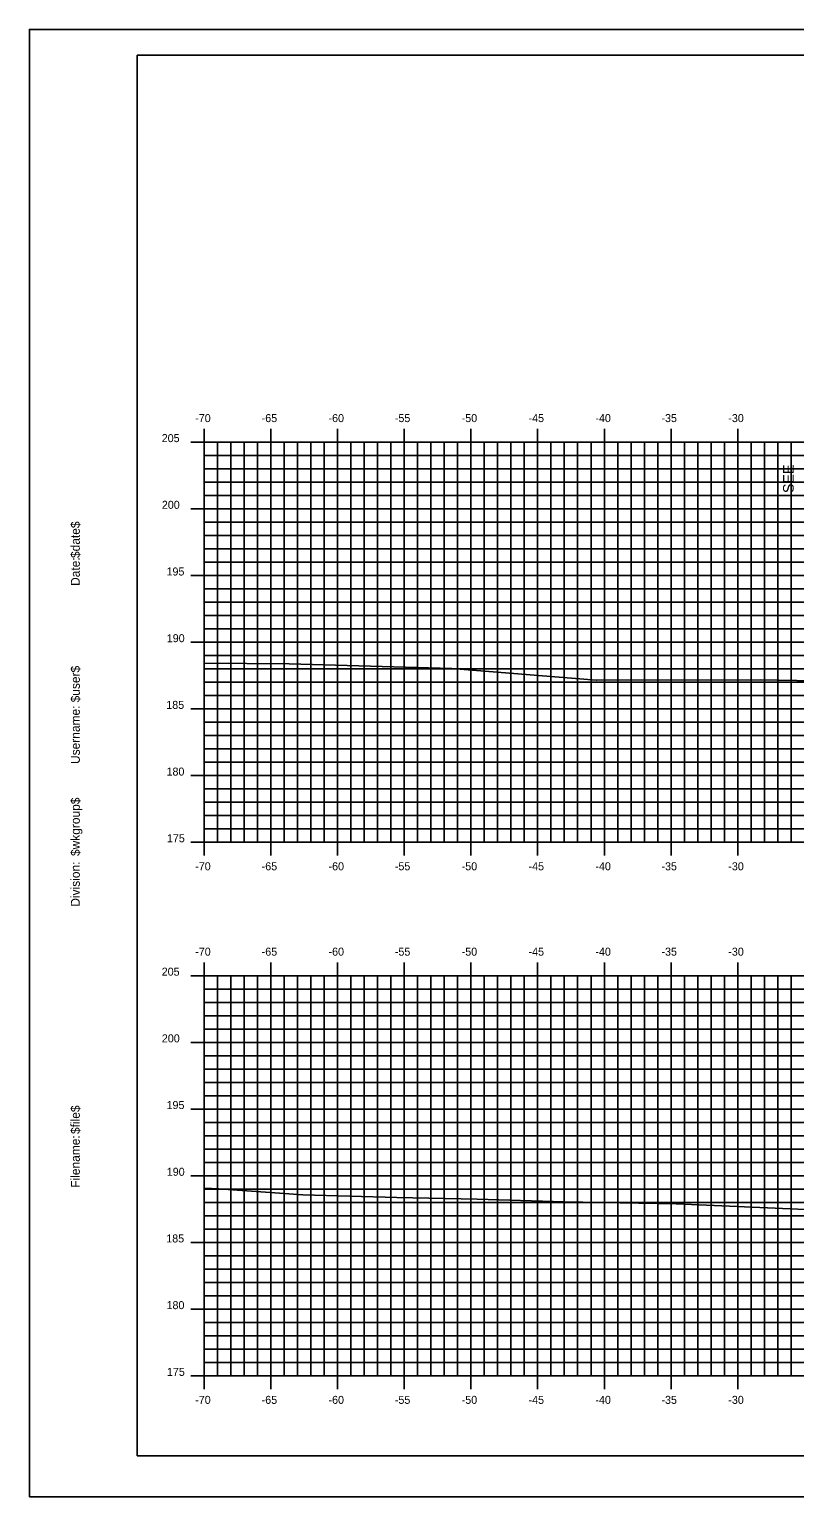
# Model space of a CAD drawing. Extents: x 1723961 to 1724133, y 459560 to 459670.
# Drawn here: x 1723961.4 to 1724018.7, y 459559.6 to 459669.6 of the extents above; entities that cross this region are included whole.
import ezdxf

# ---------------------------------------------------------------- set-up
doc = ezdxf.new("R2010")
doc.units = 0
for name, color, linetype in [('ANNOTATION', 7, 'Continuous'), ('BORDER', 7, 'Continuous'), ('H_V ANNOTATION', 7, 'Continuous'), ('MAJOR', 7, 'Continuous'), ('MINOR', 7, 'Continuous'), ('PLOT BOUNDARY', 7, 'Continuous'), ('S_Roadway_Centerline', 7, 'Continuous')]:
    doc.layers.add(name, color=color, linetype=linetype)

msp = doc.modelspace()

# ---------------------------------------------------------------- linework, layer by layer
at = {"layer": 'BORDER'}
msp.add_lwpolyline([(1723969.47, 459562.61), (1724129.47, 459562.61), (1724129.47, 459667.61), (1723969.47, 459667.61)], close=True, dxfattribs=at)
at = {"layer": 'MAJOR'}
for p, q in [((1723974.47, 459639.61), (1723974.47, 459638.61)), ((1723979.47, 459639.61), (1723979.47, 459638.61)), ((1723984.47, 459639.61), (1723984.47, 459638.61)), ((1723989.47, 459639.61), (1723989.47, 459638.61)), ((1723994.47, 459639.61), (1723994.47, 459638.61)), ((1723999.47, 459639.61), (1723999.47, 459638.61)), ((1724004.47, 459639.61), (1724004.47, 459638.61)), ((1724009.47, 459639.61), (1724009.47, 459638.61)), ((1724014.47, 459639.61), (1724014.47, 459638.61)), ((1723973.47, 459638.61), (1723974.47, 459638.61)), ((1723974.47, 459638.61), (1724114.47, 459638.61)), ((1723974.47, 459608.61), (1723974.47, 459638.61)), ((1723974.47, 459608.61), (1723974.47, 459638.61)), ((1723974.47, 459638.61), (1724114.47, 459638.61)), ((1723979.47, 459608.61), (1723979.47, 459638.61)), ((1723984.47, 459608.61), (1723984.47, 459638.61)), ((1723989.47, 459608.61), (1723989.47, 459638.61)), ((1723994.47, 459608.61), (1723994.47, 459638.61)), ((1723999.47, 459608.61), (1723999.47, 459638.61)), ((1724004.47, 459608.61), (1724004.47, 459638.61)), ((1724009.47, 459608.61), (1724009.47, 459638.61)), ((1724014.47, 459608.61), (1724014.47, 459638.61)), ((1723973.47, 459633.61), (1723974.47, 459633.61)), ((1723974.47, 459633.61), (1724114.47, 459633.61)), ((1723973.47, 459628.61), (1723974.47, 459628.61)), ((1723974.47, 459628.61), (1724114.47, 459628.61)), ((1723973.47, 459623.61), (1723974.47, 459623.61)), ((1723974.47, 459623.61), (1724114.47, 459623.61)), ((1723973.47, 459618.61), (1723974.47, 459618.61)), ((1723974.47, 459618.61), (1724114.47, 459618.61)), ((1723973.47, 459613.61), (1723974.47, 459613.61)), ((1723974.47, 459613.61), (1724114.47, 459613.61)), ((1723973.47, 459608.61), (1723974.47, 459608.61)), ((1723974.47, 459608.61), (1724114.47, 459608.61)), ((1723974.47, 459608.61), (1724114.47, 459608.61)), ((1723974.47, 459607.61), (1723974.47, 459608.61)), ((1723979.47, 459607.61), (1723979.47, 459608.61)), ((1723984.47, 459607.61), (1723984.47, 459608.61)), ((1723989.47, 459607.61), (1723989.47, 459608.61)), ((1723994.47, 459607.61), (1723994.47, 459608.61)), ((1723999.47, 459607.61), (1723999.47, 459608.61)), ((1724004.47, 459607.61), (1724004.47, 459608.61)), ((1724009.47, 459607.61), (1724009.47, 459608.61)), ((1724014.47, 459607.61), (1724014.47, 459608.61)), ((1723974.47, 459599.61), (1723974.47, 459598.61)), ((1723979.47, 459599.61), (1723979.47, 459598.61)), ((1723984.47, 459599.61), (1723984.47, 459598.61)), ((1723989.47, 459599.61), (1723989.47, 459598.61)), ((1723994.47, 459599.61), (1723994.47, 459598.61)), ((1723999.47, 459599.61), (1723999.47, 459598.61)), ((1724004.47, 459599.61), (1724004.47, 459598.61)), ((1724009.47, 459599.61), (1724009.47, 459598.61)), ((1724014.47, 459599.61), (1724014.47, 459598.61)), ((1723973.47, 459598.61), (1723974.47, 459598.61)), ((1723974.47, 459598.61), (1724114.47, 459598.61)), ((1723974.47, 459568.61), (1723974.47, 459598.61)), ((1723974.47, 459568.61), (1723974.47, 459598.61)), ((1723974.47, 459598.61), (1724114.47, 459598.61)), ((1723979.47, 459568.61), (1723979.47, 459598.61)), ((1723984.47, 459568.61), (1723984.47, 459598.61)), ((1723989.47, 459568.61), (1723989.47, 459598.61)), ((1723994.47, 459568.61), (1723994.47, 459598.61)), ((1723999.47, 459568.61), (1723999.47, 459598.61)), ((1724004.47, 459568.61), (1724004.47, 459598.61)), ((1724009.47, 459568.61), (1724009.47, 459598.61)), ((1724014.47, 459568.61), (1724014.47, 459598.61)), ((1723973.47, 459593.61), (1723974.47, 459593.61)), ((1723974.47, 459593.61), (1724114.47, 459593.61)), ((1723973.47, 459588.61), (1723974.47, 459588.61)), ((1723974.47, 459588.61), (1724114.47, 459588.61)), ((1723973.47, 459583.61), (1723974.47, 459583.61)), ((1723974.47, 459583.61), (1724114.47, 459583.61)), ((1723973.47, 459578.61), (1723974.47, 459578.61)), ((1723974.47, 459578.61), (1724114.47, 459578.61)), ((1723973.47, 459573.61), (1723974.47, 459573.61)), ((1723974.47, 459573.61), (1724114.47, 459573.61)), ((1723973.47, 459568.61), (1723974.47, 459568.61)), ((1723974.47, 459568.61), (1724114.47, 459568.61)), ((1723974.47, 459568.61), (1724114.47, 459568.61)), ((1723974.47, 459567.61), (1723974.47, 459568.61)), ((1723979.47, 459567.61), (1723979.47, 459568.61)), ((1723984.47, 459567.61), (1723984.47, 459568.61)), ((1723989.47, 459567.61), (1723989.47, 459568.61)), ((1723994.47, 459567.61), (1723994.47, 459568.61)), ((1723999.47, 459567.61), (1723999.47, 459568.61)), ((1724004.47, 459567.61), (1724004.47, 459568.61)), ((1724009.47, 459567.61), (1724009.47, 459568.61)), ((1724014.47, 459567.61), (1724014.47, 459568.61))]:
    msp.add_line(p, q, dxfattribs=at)
at = {"layer": 'MINOR'}
for p, q in [((1723975.47, 459608.61), (1723975.47, 459638.61)), ((1723976.47, 459608.61), (1723976.47, 459638.61)), ((1723977.47, 459608.61), (1723977.47, 459638.61)), ((1723978.47, 459608.61), (1723978.47, 459638.61)), ((1723980.47, 459608.61), (1723980.47, 459638.61)), ((1723981.47, 459608.61), (1723981.47, 459638.61)), ((1723982.47, 459608.61), (1723982.47, 459638.61)), ((1723983.47, 459608.61), (1723983.47, 459638.61)), ((1723985.47, 459608.61), (1723985.47, 459638.61)), ((1723986.47, 459608.61), (1723986.47, 459638.61)), ((1723987.47, 459608.61), (1723987.47, 459638.61)), ((1723988.47, 459608.61), (1723988.47, 459638.61)), ((1723990.47, 459608.61), (1723990.47, 459638.61)), ((1723991.47, 459608.61), (1723991.47, 459638.61)), ((1723992.47, 459608.61), (1723992.47, 459638.61)), ((1723993.47, 459608.61), (1723993.47, 459638.61)), ((1723995.47, 459608.61), (1723995.47, 459638.61)), ((1723996.47, 459608.61), (1723996.47, 459638.61)), ((1723997.47, 459608.61), (1723997.47, 459638.61)), ((1723998.47, 459608.61), (1723998.47, 459638.61)), ((1724000.47, 459608.61), (1724000.47, 459638.61)), ((1724001.47, 459608.61), (1724001.47, 459638.61)), ((1724002.47, 459608.61), (1724002.47, 459638.61)), ((1724003.47, 459608.61), (1724003.47, 459638.61)), ((1724005.47, 459608.61), (1724005.47, 459638.61)), ((1724006.47, 459608.61), (1724006.47, 459638.61)), ((1724007.47, 459608.61), (1724007.47, 459638.61)), ((1724008.47, 459608.61), (1724008.47, 459638.61)), ((1724010.47, 459608.61), (1724010.47, 459638.61)), ((1724011.47, 459608.61), (1724011.47, 459638.61)), ((1724012.47, 459608.61), (1724012.47, 459638.61)), ((1724013.47, 459608.61), (1724013.47, 459638.61)), ((1724015.47, 459608.61), (1724015.47, 459638.61)), ((1724016.47, 459608.61), (1724016.47, 459638.61)), ((1724017.47, 459608.61), (1724017.47, 459638.61)), ((1724018.47, 459608.61), (1724018.47, 459638.61)), ((1723974.47, 459637.61), (1724114.47, 459637.61)), ((1723974.47, 459637.61), (1723975.48, 459637.61)), ((1723974.47, 459636.61), (1724114.47, 459636.61)), ((1723974.47, 459636.61), (1723975.48, 459636.61)), ((1723974.47, 459635.61), (1724114.47, 459635.61)), ((1723974.47, 459635.61), (1723975.48, 459635.61)), ((1723974.47, 459634.61), (1724114.47, 459634.61)), ((1723974.47, 459634.61), (1723975.48, 459634.61)), ((1723974.47, 459632.61), (1724114.47, 459632.61)), ((1723974.47, 459632.61), (1723975.48, 459632.61)), ((1723974.47, 459631.61), (1724114.47, 459631.61)), ((1723974.47, 459631.61), (1723975.48, 459631.61)), ((1723974.47, 459630.61), (1724114.47, 459630.61)), ((1723974.47, 459630.61), (1723975.48, 459630.61)), ((1723974.47, 459629.61), (1724114.47, 459629.61)), ((1723974.47, 459629.61), (1723975.48, 459629.61)), ((1723974.47, 459627.61), (1724114.47, 459627.61)), ((1723974.47, 459627.61), (1723975.48, 459627.61)), ((1723974.47, 459626.61), (1724114.47, 459626.61)), ((1723974.47, 459626.61), (1723975.48, 459626.61)), ((1723974.47, 459625.61), (1724114.47, 459625.61)), ((1723974.47, 459625.61), (1723975.48, 459625.61)), ((1723974.47, 459624.61), (1724114.47, 459624.61)), ((1723974.47, 459624.61), (1723975.48, 459624.61)), ((1723974.47, 459622.61), (1724114.47, 459622.61)), ((1723974.47, 459622.61), (1723975.48, 459622.61)), ((1723974.47, 459621.61), (1724114.47, 459621.61)), ((1723974.47, 459621.61), (1723975.48, 459621.61)), ((1723974.47, 459620.61), (1724114.47, 459620.61)), ((1723974.47, 459620.61), (1723975.48, 459620.61)), ((1723974.47, 459619.61), (1724114.47, 459619.61)), ((1723974.47, 459619.61), (1723975.48, 459619.61)), ((1723974.47, 459617.61), (1724114.47, 459617.61)), ((1723974.47, 459617.61), (1723975.48, 459617.61)), ((1723974.47, 459616.61), (1724114.47, 459616.61)), ((1723974.47, 459616.61), (1723975.48, 459616.61)), ((1723974.47, 459615.61), (1724114.47, 459615.61)), ((1723974.47, 459615.61), (1723975.48, 459615.61)), ((1723974.47, 459614.61), (1724114.47, 459614.61)), ((1723974.47, 459614.61), (1723975.48, 459614.61)), ((1723974.47, 459612.61), (1724114.47, 459612.61)), ((1723974.47, 459612.61), (1723975.48, 459612.61)), ((1723974.47, 459611.61), (1724114.47, 459611.61)), ((1723974.47, 459611.61), (1723975.48, 459611.61)), ((1723974.47, 459610.61), (1724114.47, 459610.61)), ((1723974.47, 459610.61), (1723975.48, 459610.61)), ((1723974.47, 459609.61), (1724114.47, 459609.61)), ((1723974.47, 459609.61), (1723975.48, 459609.61)), ((1723974.47, 459568.61), (1723974.47, 459598.61)), ((1723974.47, 459597.61), (1724114.47, 459597.61)), ((1723974.47, 459597.61), (1723975.48, 459597.61)), ((1723975.47, 459568.61), (1723975.47, 459598.61)), ((1723976.47, 459568.61), (1723976.47, 459598.61)), ((1723977.47, 459568.61), (1723977.47, 459598.61)), ((1723978.47, 459568.61), (1723978.47, 459598.61)), ((1723980.47, 459568.61), (1723980.47, 459598.61)), ((1723981.47, 459568.61), (1723981.47, 459598.61)), ((1723982.47, 459568.61), (1723982.47, 459598.61)), ((1723983.47, 459568.61), (1723983.47, 459598.61)), ((1723985.47, 459568.61), (1723985.47, 459598.61)), ((1723986.47, 459568.61), (1723986.47, 459598.61)), ((1723987.47, 459568.61), (1723987.47, 459598.61)), ((1723988.47, 459568.61), (1723988.47, 459598.61)), ((1723990.47, 459568.61), (1723990.47, 459598.61)), ((1723991.47, 459568.61), (1723991.47, 459598.61)), ((1723992.47, 459568.61), (1723992.47, 459598.61)), ((1723993.47, 459568.61), (1723993.47, 459598.61)), ((1723995.47, 459568.61), (1723995.47, 459598.61)), ((1723996.47, 459568.61), (1723996.47, 459598.61)), ((1723997.47, 459568.61), (1723997.47, 459598.61)), ((1723998.47, 459568.61), (1723998.47, 459598.61)), ((1724000.47, 459568.61), (1724000.47, 459598.61)), ((1724001.47, 459568.61), (1724001.47, 459598.61)), ((1724002.47, 459568.61), (1724002.47, 459598.61)), ((1724003.47, 459568.61), (1724003.47, 459598.61)), ((1724005.47, 459568.61), (1724005.47, 459598.61)), ((1724006.47, 459568.61), (1724006.47, 459598.61)), ((1724007.47, 459568.61), (1724007.47, 459598.61)), ((1724008.47, 459568.61), (1724008.47, 459598.61)), ((1724010.47, 459568.61), (1724010.47, 459598.61)), ((1724011.47, 459568.61), (1724011.47, 459598.61)), ((1724012.47, 459568.61), (1724012.47, 459598.61)), ((1724013.47, 459568.61), (1724013.47, 459598.61)), ((1724015.47, 459568.61), (1724015.47, 459598.61)), ((1724016.47, 459568.61), (1724016.47, 459598.61)), ((1724017.47, 459568.61), (1724017.47, 459598.61)), ((1724018.47, 459568.61), (1724018.47, 459598.61)), ((1723974.47, 459596.61), (1724114.47, 459596.61)), ((1723974.47, 459596.61), (1723975.48, 459596.61)), ((1723974.47, 459595.61), (1724114.47, 459595.61)), ((1723974.47, 459595.61), (1723975.48, 459595.61)), ((1723974.47, 459594.61), (1724114.47, 459594.61)), ((1723974.47, 459594.61), (1723975.48, 459594.61)), ((1723974.47, 459592.61), (1724114.47, 459592.61)), ((1723974.47, 459591.61), (1724114.47, 459591.61)), ((1723974.47, 459590.61), (1724114.47, 459590.61)), ((1723974.47, 459589.61), (1724114.47, 459589.61)), ((1723974.47, 459589.61), (1723975.48, 459589.61)), ((1723974.47, 459587.61), (1724114.47, 459587.61)), ((1723974.47, 459587.61), (1723975.48, 459587.61)), ((1723974.47, 459586.61), (1724114.47, 459586.61)), ((1723974.47, 459586.61), (1723975.48, 459586.61)), ((1723974.47, 459585.61), (1724114.47, 459585.61)), ((1723974.47, 459585.61), (1723975.48, 459585.61)), ((1723974.47, 459584.61), (1724114.47, 459584.61)), ((1723974.47, 459584.61), (1723975.48, 459584.61)), ((1723974.47, 459582.61), (1724114.47, 459582.61)), ((1723974.47, 459582.61), (1723975.48, 459582.61)), ((1723974.47, 459581.61), (1724114.47, 459581.61)), ((1723974.47, 459581.61), (1723975.48, 459581.61)), ((1723974.47, 459580.61), (1724114.47, 459580.61)), ((1723974.47, 459580.61), (1723975.48, 459580.61)), ((1723974.47, 459579.61), (1724114.47, 459579.61)), ((1723974.47, 459579.61), (1723975.48, 459579.61)), ((1723974.47, 459577.61), (1724114.47, 459577.61)), ((1723974.47, 459577.61), (1723975.48, 459577.61)), ((1723974.47, 459576.61), (1724114.47, 459576.61)), ((1723974.47, 459576.61), (1723975.48, 459576.61)), ((1723974.47, 459575.61), (1724114.47, 459575.61)), ((1723974.47, 459575.61), (1723975.48, 459575.61)), ((1723974.47, 459574.61), (1724114.47, 459574.61)), ((1723974.47, 459574.61), (1723975.48, 459574.61)), ((1723974.47, 459572.61), (1724114.47, 459572.61)), ((1723974.47, 459572.61), (1723975.48, 459572.61)), ((1723974.47, 459571.61), (1724114.47, 459571.61)), ((1723974.47, 459571.61), (1723975.48, 459571.61)), ((1723974.47, 459570.61), (1724114.47, 459570.61)), ((1723974.47, 459570.61), (1723975.48, 459570.61)), ((1723974.47, 459569.61), (1724114.47, 459569.61)), ((1723974.47, 459569.61), (1723975.48, 459569.61))]:
    msp.add_line(p, q, dxfattribs=at)
at = {"layer": 'PLOT BOUNDARY'}
msp.add_lwpolyline([(1723961.38, 459559.55), (1724131.38, 459559.55), (1724131.38, 459669.55), (1723961.38, 459669.55)], close=True, dxfattribs=at)
at = {"layer": 'S_Roadway_Centerline'}
for points in [[(1723974.47, 459622.03), (1723980.84, 459621.98), (1723993.04, 459621.63), (1724003.85, 459620.76), (1724003.88, 459620.76), (1724016.2, 459620.8), (1724025.64, 459620.62), (1724029.82, 459620.46), (1724046.7, 459619.91), (1724055.65, 459619.73), (1724062.61, 459619.53), (1724079.62, 459618.91), (1724085.94, 459618.83), (1724091.01, 459618.73), (1724104.13, 459618.53), (1724113.51, 459618.18), (1724114.47, 459618.14)], [(1723974.47, 459582.67), (1723975.57, 459582.63), (1723981.88, 459582.17), (1723988.93, 459581.99), (1723994.93, 459581.86), (1724001.47, 459581.65), (1724009.84, 459581.51), (1724028.66, 459580.69), (1724030.53, 459580.58), (1724048.38, 459580.09), (1724051.97, 459579.99), (1724052.88, 459579.98), (1724072.14, 459579.63), (1724078.31, 459579.39), (1724087.23, 459578.82), (1724094.37, 459578.66), (1724105, 459578.51), (1724110.8, 459578.47), (1724114.47, 459578.4)]]:
    msp.add_lwpolyline(points, dxfattribs=at)

# ---------------------------------------------------------------- texts
at = {"layer": 'ANNOTATION'}
msp.add_text('SEE', height=0.8, rotation=90, dxfattribs=at).set_placement((1724018.66, 459634.79))
at = {"layer": 'BORDER'}
for s, p in [('$date$', (1723965.16, 459629.92)), ('Date:', (1723965.16, 459627.83)), ('$user$', (1723965.16, 459619.1)), ('Username:', (1723965.16, 459614.48)), ('$wkgroup$', (1723965.16, 459607.58)), ('Division:', (1723965.16, 459603.78)), ('$file$', (1723965.16, 459586.74)), ('Filename:', (1723965.16, 459582.71))]:
    msp.add_text(s, height=0.67, rotation=90, dxfattribs=at).set_placement(p)
at = {"layer": 'H_V ANNOTATION'}
for s, p in [('-70', (1723973.81, 459640.11)), ('-65', (1723978.79, 459640.11)), ('-60', (1723983.8, 459640.11)), ('-55', (1723988.77, 459640.11)), ('-50', (1723993.78, 459640.11)), ('-45', (1723998.79, 459640.11)), ('-40', (1724003.8, 459640.11)), ('-35', (1724008.75, 459640.11)), ('-30', (1724013.76, 459640.11)), ('205', (1723971.3, 459638.61)), ('200', (1723971.31, 459633.61)), ('195', (1723971.66, 459628.61)), ('190', (1723971.68, 459623.61)), ('185', (1723971.64, 459618.61)), ('180', (1723971.66, 459613.61)), ('175', (1723971.69, 459608.61)), ('-70', (1723973.81, 459606.51)), ('-65', (1723978.79, 459606.51)), ('-60', (1723983.8, 459606.51)), ('-55', (1723988.77, 459606.51)), ('-50', (1723993.78, 459606.51)), ('-45', (1723998.79, 459606.51)), ('-40', (1724003.8, 459606.51)), ('-35', (1724008.75, 459606.51)), ('-30', (1724013.76, 459606.51)), ('-70', (1723973.81, 459600.11)), ('-65', (1723978.79, 459600.11)), ('-60', (1723983.8, 459600.11)), ('-55', (1723988.77, 459600.11)), ('-50', (1723993.78, 459600.11)), ('-45', (1723998.79, 459600.11)), ('-40', (1724003.8, 459600.11)), ('-35', (1724008.75, 459600.11)), ('-30', (1724013.76, 459600.11)), ('205', (1723971.3, 459598.61)), ('200', (1723971.31, 459593.61)), ('195', (1723971.66, 459588.61)), ('190', (1723971.68, 459583.61)), ('185', (1723971.64, 459578.61)), ('180', (1723971.66, 459573.61)), ('175', (1723971.69, 459568.61)), ('-70', (1723973.81, 459566.51)), ('-65', (1723978.79, 459566.51)), ('-60', (1723983.8, 459566.51)), ('-55', (1723988.77, 459566.51)), ('-50', (1723993.78, 459566.51)), ('-45', (1723998.79, 459566.51)), ('-40', (1724003.8, 459566.51)), ('-35', (1724008.75, 459566.51)), ('-30', (1724013.76, 459566.51))]:
    msp.add_text(s, height=0.6, dxfattribs=at).set_placement(p)
at = {"layer": 'MAJOR'}
for p in [(1723974.47, 459608.61), (1723974.47, 459568.61)]:
    msp.add_text('-', height=0.006, dxfattribs=at).set_placement(p)

doc.saveas('drawing.dxf')
